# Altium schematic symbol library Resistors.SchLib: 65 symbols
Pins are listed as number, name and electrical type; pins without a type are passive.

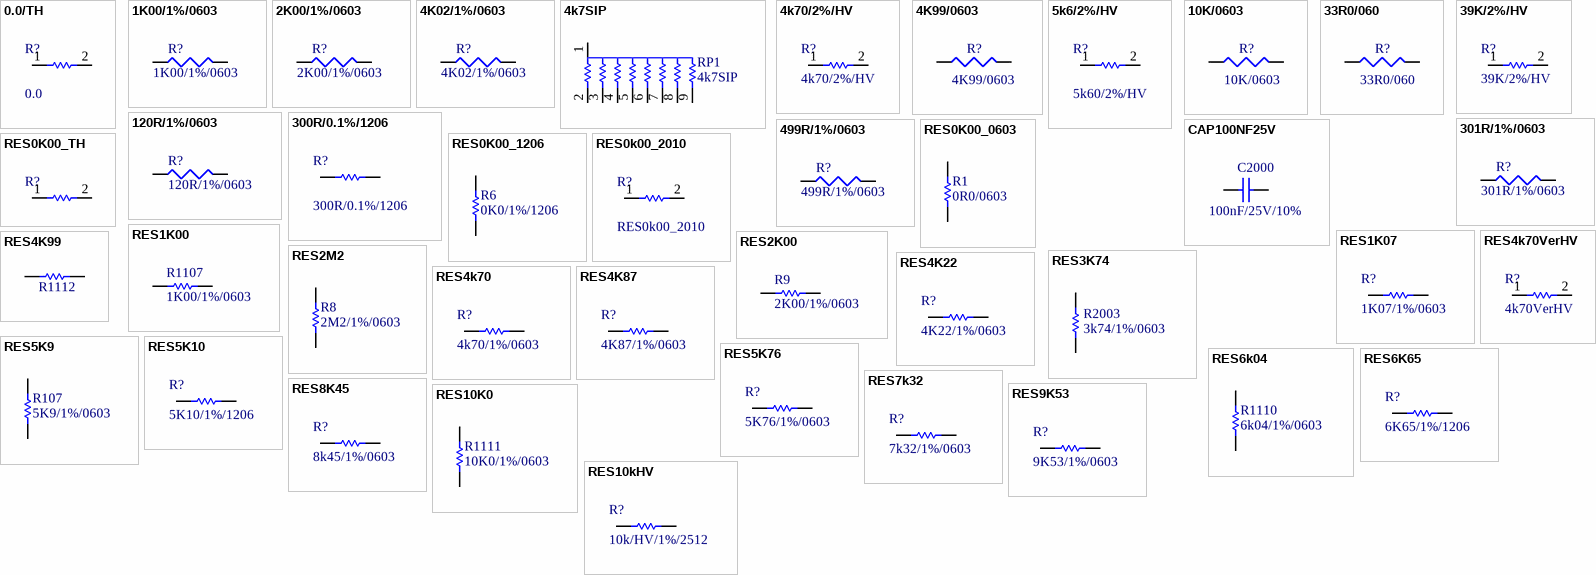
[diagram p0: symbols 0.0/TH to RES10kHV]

## 0.0/TH
designator R?, comment 0.0
0 Ohms Jumper 0.167W, 1/6W Through Hole Resistor Axial Carbon Film; MFG PN: ZOR-12-R-52-0R; DK PN: 0.0ETR-ND; MFG: Yageo; Comment_1: 0.0/TH
footprint Model Name (Footprint not found)
footprint ZEROOHM
pins: 1, 2
1 alternate drawing of the same symbol

## 1K00/1%/0603
designator R?
1 kOhms ±1% 0.1W, 1/10W Chip Resistor 0603 (1608 Metric) Moisture Resistant Thick Film; MFG: Yeago; MFG PN: RC0603FR-071KL; DK PN: 311-1.00KHRCT-ND
footprint 0603
pins: 1, 2

## 2K00/1%/0603
designator R?
2 kOhms ±1% 0.1W, 1/10W Chip Resistor 0603 (1608 Metric) Moisture Resistant Thick Film; MFG: Yeago; MFG PN: RC0603FR-072KL; DK PN: 311-2.00KHRCT-ND
footprint 0603
pins: 1, 2

## 4K02/1%/0603
designator R?
4.02 kOhms ±1% 0.1W, 1/10W Chip Resistor 0603 (1608 Metric) Moisture Resistant Thick Film; MFG: Yeago; MFG PN: RC0603FR-074K02L; DK PN: 311-4.02KHRCT-ND
footprint 0603
pins: 1, 2

## 4k7SIP
designator RP1
4.7k Ohm ±2% 200mW Power Per Element Bussed Resistor Network/Array ±100ppm/°C 9-SIP; MFG: Bournes; MFG PN: 4609X-101-472LF; DK PN: 4609X-101-472LF-ND
footprint SIP9
pins: 1, 2, 3, 4, 5, 6, 7, 8, 9

## 4k70/2%/HV
designator R?  Comment_1: 4k70/2%/HV  (hidden comment: *)
4.7 kOhms ±2% 1W Chip Resistor MELF, 0207 Anti-Sulfur, Automotive AEC-Q200, Pulse Withstanding Carbon Film; MFG PN: CMB02070X4701GB200; DK PN: CMB-4.7KCT-ND; MFG: Vishay
footprint CMB0207
pins: 1, 2
1 alternate drawing of the same symbol

## 4K99/0603
designator R?
RES 4.99K OHM 1/10W 1% 0603 SMD; MFG: Dale/Vishay; MFG PN: CRCW06034K99FKEAC; DK PN: 541-3985-1-ND
footprint 0603
pins: 1, 2

## 5k6/2%/HV
designator R?, comment 5k60/2%/HV
5.6 kOhms ±2% 1W Chip Resistor MELF, 0207 Anti-Sulfur, Automotive AEC-Q200, Pulse Withstanding Carbon Film; MFG PN: CMB02070X5601GB200; DK PN: CMB-5.6KCT-ND; MFG: Vishay
footprint CMB0207
pins: 1, 2
1 alternate drawing of the same symbol

## 10K/0603
designator R?
RES 10.0K OHM 1/10W 1% 0603 SMD; MFG: Dale/Vishay; MFG PN: CRCW060310K0FKEA; DK PN: 541-10.0KHCT-ND
footprint 0603
pins: 1, 2

## 33R0/060
designator R?
33 Ohms ±1% 0.1W, 1/10W Chip Resistor 0603 (1608 Metric) Moisture Resistant Thick Film; MFG: Yaego; MFG PN: RC0603FR-0733RL; DK PN: 311-33.0HRCT-ND
footprint 0603
pins: 1, 2

## 39K/2%/HV
designator R?
39 kOhms ±2% 1W Chip Resistor MELF, 0207 Anti-Sulfur, Automotive AEC-Q200, Pulse Withstanding Carbon Film; MFG PN: CMB02070X3902GB200; DK PN: CMB-39KCT-ND; MFG: Vishay
footprint CMB0207
pins: 1, 2
1 alternate drawing of the same symbol

## 120R/1%/0603
designator R?
120 Ohms ±1% 0.1W, 1/10W Chip Resistor 0603 (1608 Metric) Moisture Resistant Thick Film; MFG: Yaego; MFG PN: RC0603FR-07120RL; DK PN: 311-120HRCT-ND
footprint 0603
pins: 1, 2

## 300R/0.1%/1206
designator R?
300 Ohms ±0.1% 0.25W, 1/4W Chip Resistor 1206 (3216 Metric) Automotive AEC-Q200 Thin Film; MFG PN: ERA-8AEB301V; DK PN: P300BCCT-ND; MFG: Panasonic
footprint MY1206
pins: 1, 2
1 alternate drawing of the same symbol

## 301R/1%/0603
designator R?
301 Ohms ±1% 0.1W, 1/10W Chip Resistor 0603 (1608 Metric) Moisture Resistant Thick Film; MFG: Yeago; MFG PN: RC0603FR-07301RL; DK PN: 311-301HRCT-ND
footprint 0603
pins: 1, 2

## 499R/1%/0603
designator R?
499 Ohms ±1% 0.1W, 1/10W Chip Resistor 0603 (1608 Metric) Moisture Resistant Thick Film; MFG: Yeago; MFG PN: RC0603FR-07499RL; DK PN: 311-499HRCT-ND
footprint 0603
pins: 1, 2

## CAP100NF25V
designator C2000, comment 100nF/25V/10%
0.1µF ±10% 25V Ceramic Capacitor X7R 0603 (1608 Metric); MFG PN: 06033C104KAT2A; DK PN: 478-3714-1-ND; MFG: AVX
footprint MY0603
pins: 1, 2

## RES0K00_0603
designator R1, comment 0R0/0603
0.0 Ohm Jumper 0.1W, 1/10W Chip Resistor 0603 (1608 Metric) Moisture Resistant Thick Film; MFG PN: RC0603FR-070RL; DK PN: 311-0.0HRTR-ND; MFG: Yageo
footprint MY0603
pins: 1, 2
1 alternate drawing of the same symbol

## RES0K00_1206
designator R6  Comment_1: 0K0/1%/1206  (hidden comment: RES0K00_1206)
0.0 Ohm Jumper 0.25W, 1/4W Chip Resistor 1206 (3216 Metric) Moisture Resistant Thick Film; MFG PN: RC1206JR-070RL; DK PN: 311-0.0ERCT-ND; MFG: Yageo
footprint MY1206
pins: 1, 2
1 alternate drawing of the same symbol

## RES0k00_2010
designator R?
0 Ohms Jumper 0.75W, 3/4W Chip Resistor 2010 (5025 Metric) Automotive AEC-Q200 Thick Film; MFG PN: RMCF2010ZT0R00; DK PN: RMCF2010ZT0R00TR-ND; MFG: Stackpole
footprint CMB0207
pins: 1, 2
1 alternate drawing of the same symbol

## RES0K00_TH
designator R?, comment 0.0  (value not drawn)
0 Ohms Jumper 0.167W, 1/6W Through Hole Resistor Axial Carbon Film; MFG PN: ZOR-12-R-52-0R; DK PN: 0.0ETR-ND; MFG: Yageo
footprint JUMPER0.5
pins: 1, 2
1 alternate drawing of the same symbol

## RES1K00
designator R1107, comment 1K00/1%/0603
1.00k Ohm ±1% 0.1W, 1/10W Chip Resistor 0603 (1608 Metric) Moisture Resistant Thick Film; MFG PN: RC0603FR-071KL; DK PN: 311-1.00KHRTR-ND; MFG: Yageo
footprint MY0603
pins: 1, 2
1 alternate drawing of the same symbol

## RES1K07
designator R?, comment 1K07/1%/0603
1.00k Ohm ±1% 0.1W, 1/10W Chip Resistor 0603 (1608 Metric) Moisture Resistant Thick Film; MFG PN: RC0603FR-071K07L; DK PN: 311-1.07KHRTR-ND; MFG: Yageo
footprint MY0603
pins: 1, 2
1 alternate drawing of the same symbol

## RES2K00
designator R9, comment 2K00/1%/0603
2.00k Ohm ±1% 0.1W, 1/10W Chip Resistor 0603 (1608 Metric) Moisture Resistant Thick Film; MFG PN: RC0603FR-072KL; DK PN: 311-2.00KHRTR-ND; MFG: Yageo
footprint MY0603
pins: 1, 2
1 alternate drawing of the same symbol

## RES2M2
designator R8, comment 2M2/1%/0603
2.2M Ohm ±1% 0.1W, 1/10W Chip Resistor 0603 (1608 Metric) Moisture Resistant Thick Film; MFG PN: RC0603FR-072M2L; DK PN: YAG3329CT-ND; MFG: Yageo
footprint MY0603
pins: 1, 2
1 alternate drawing of the same symbol

## RES3K74
designator R2003, comment 3k74/1%/0603
3.74k Ohm ±1% 0.1W, 1/10W Chip Resistor 0603 (1608 Metric) Moisture Resistant Thick Film; MFG PN: RC0603FR-073K74L; DK PN: 311-3.74KHRTR-ND; MFG: Yageo
footprint MY0603
pins: 1, 2
1 alternate drawing of the same symbol

## RES4K22
designator R?, comment 4K22/1%/0603
4.22k Ohm ±1% 0.1W, 1/10W Chip Resistor 0603 (1608 Metric) Moisture Resistant Thick Film; MFG PN: RC0603FR-074K22L; DK PN: 311-4.22KHRTR-ND; MFG: Yageo
footprint MY0603
pins: 1, 2
1 alternate drawing of the same symbol

## RES4k70
designator R?, comment 4k70/1%/0603
4.7k Ohm ±1% 0.1W, 1/10W Chip Resistor 0603 (1608 Metric) Moisture Resistant Thick Film; MFG PN: RC0603FR-074K7L; DK PN: 311-4.70KHRTR-ND; MFG: Yageo
footprint MY0603
pins: 1, 2
1 alternate drawing of the same symbol

## RES4k70VerHV
designator R?, comment 4k70VerHV
4.7 kOhms ±5% 1W Through Hole Resistor Axial Flame Retardant Coating, Pulse Withstanding, Safety Metal Film; MFG PN: ASRM1JA4K70; DK PN: ASRM1JA4K70CT-ND; MFG: Stackpole
footprint ASR1_VERT
pins: 1, 2
1 alternate drawing of the same symbol

## RES4K87
designator R?, comment 4K87/1%/0603
4.87k Ohm ±1% 0.1W, 1/10W Chip Resistor 0603 (1608 Metric) Moisture Resistant Thick Film; MFG PN: RC0603FR-074K87L; DK PN: 311-4.87KHRTR-ND; MFG: Yageo
footprint MY0603
pins: 1, 2
1 alternate drawing of the same symbol

## RES4K99
designator R1112  (value not drawn)
4.99k Ohm ±1% 0.1W, 1/10W Chip Resistor 0603 (1608 Metric) Moisture Resistant Thick Film; MFG PN: RC0603FR-074K99L; DK PN: 311-4.99KHRTR-ND; MFG: Yageo; Comment_1: 4K99/1%/0603
footprint MY0603
pins: 1, 2
1 alternate drawing of the same symbol

## RES5K9
designator R107, comment 5K9/1%/0603
5.9k Ohm ±1% 0.1W, 1/10W Chip Resistor 0603 (1608 Metric) Moisture Resistant Thick Film; MFG PN: RC0603FR-075K9L; DK PN: 311-5.90KHRTR-ND; MFG: Yageo
footprint MY0603
pins: 1, 2
1 alternate drawing of the same symbol

## RES5K10
designator R?, comment 5K10/1%/1206
5.1k Ohm ±1% 0.25W, 1/4W Chip Resistor 1206 (3216 Metric) Automotive AEC-Q200, High Voltage Thick Film; MFG PN: KTR18EZPF5101; DK PN: RHM5.10KAICT-ND; MFG: Rohm
footprint MY1206
pins: 1, 2
1 alternate drawing of the same symbol

## RES5K76
designator R?, comment 5K76/1%/0603
5.76k Ohm ±1% 0.1W, 1/10W Chip Resistor 0603 (1608 Metric) Moisture Resistant Thick Film; MFG PN: RC0603FR-075K76L; DK PN: 311-5.76KHRCT-ND; MFG: Yageo
footprint MY0603
pins: 1, 2
1 alternate drawing of the same symbol

## RES6k04
designator R1110, comment 6k04/1%/0603
6.04 kOhms ±1% 0.1W, 1/10W Chip Resistor 0603 (1608 Metric) Automotive AEC-Q200 Thick Film; MFG PN: ERJ-3EKF6041V; DK PN: P6.04KHDKR-ND; MFG: Panasonic
footprint MY0603
pins: 1, 2
1 alternate drawing of the same symbol

## RES6K65
designator R?, comment 6K65/1%/1206
6.65 kOhms ±1% 0.25W, 1/4W Chip Resistor 1206 (3216 Metric) Automotive AEC-Q200, High Voltage Thick Film; MFG PN: KTR18EZPF6651; DK PN: RHM6.65KAICT-ND; MFG: Rohm
footprint MY1206
pins: 1, 2
1 alternate drawing of the same symbol

## RES7k32
designator R?, comment 7k32/1%/0603
7.32 kOhms ±1% 0.1W, 1/10W Chip Resistor 0603 (1608 Metric) Moisture Resistant Thick Film; MFG PN: RC0603FR-077K32L; DK PN: 311-7.32KHRCT-ND; MFG: Yageo
footprint MY0603
pins: 1, 2
1 alternate drawing of the same symbol

## RES8K45
designator R?, comment 8k45/1%/0603
8.45k Ohm ±1% 0.1W, 1/10W Chip Resistor 0603 (1608 Metric) Moisture Resistant Thick Film; MFG PN: RC0603FR-078K45L; DK PN: 311-8.45KHRTR-ND; MFG: Yageo
footprint MY0603
pins: 1, 2
1 alternate drawing of the same symbol

## RES9K53
designator R?, comment 9K53/1%/0603
9.53k Ohm ±1% 0.1W, 1/10W Chip Resistor 0603 (1608 Metric) Moisture Resistant Thick Film; MFG PN: RC0603FR-079K53L; DK PN: 311-9.53KHRTR-ND; MFG: Yageo
footprint MY0603
pins: 1, 2
1 alternate drawing of the same symbol

## RES10K0
designator R1111, comment 10K0/1%/0603
10k Ohm ±1% 0.1W, 1/10W Chip Resistor 0603 (1608 Metric) Moisture Resistant Thick Film; MFG PN: RC0603FR-0710KL; DK PN: 311-10.0KHRTR-ND; MFG: Yageo
footprint MY0603
pins: 1, 2
1 alternate drawing of the same symbol

## RES10kHV
designator R?, comment 10k/HV/1%/2512
10k Ohm ±1% 2W Chip Resistor 2512 (6432 Metric) High Voltage, Pulse Withstanding Thick Film; MFG PN: HVCB2512FDD10K0; DK PN: HVCB2512FDD10K0TR-ND; MFG: Stackpole
footprint HVC2512
pins: 1, 2
1 alternate drawing of the same symbol

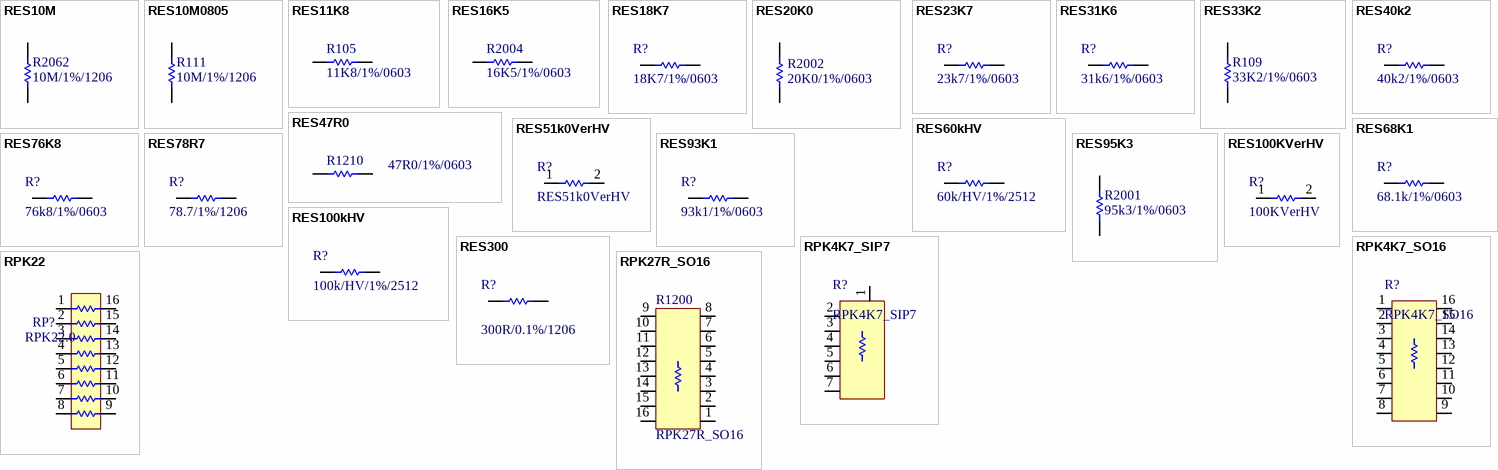
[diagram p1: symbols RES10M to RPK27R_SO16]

## RES10M
designator R2062, comment 10M/1%/1206
10 MOhms ±1% 0.25W, 1/4W Chip Resistor 1206 (3216 Metric) Automotive AEC-Q200, High Voltage Thick Film; MFG PN: KTR18EZPF1005; DK PN: RHM10.0MAICT-ND; MFG: Rohm
footprint MY1206
pins: 1, 2
1 alternate drawing of the same symbol

## RES10M0805
designator R111, comment 10M/1%/1206
10 MOhms ±1% 0.125W, 1/8W Chip Resistor 0805 (2012 Metric) Moisture Resistant Thick Film; MFG PN: RC2012F106CS; DK PN: 1276-5465-2-ND; MFG: Samsung
footprint MY0805
pins: 1, 2
1 alternate drawing of the same symbol

## RES11K8
designator R105, comment 11K8/1%/0603
11.8k Ohm ±1% 0.1W, 1/10W Chip Resistor 0603 (1608 Metric) Moisture Resistant Thick Film; MFG PN: 311-11.8KHRTR-ND; DK PN: RC0603FR-0711K8L; MFG: Yageo
footprint MY0603
pins: 1, 2
1 alternate drawing of the same symbol

## RES16K5
designator R2004, comment 16K5/1%/0603
16.5k Ohm ±1% 0.1W, 1/10W Chip Resistor 0603 (1608 Metric) Moisture Resistant Thick Film; MFG PN: RC0603FR-0716K5L; DK PN: 311-16.5KHRTR-ND; MFG: Yageo
footprint MY0603
pins: 1, 2
1 alternate drawing of the same symbol

## RES18K7
designator R?, comment 18K7/1%/0603
18.7k Ohm ±1% 0.1W, 1/10W Chip Resistor 0603 (1608 Metric) Moisture Resistant Thick Film; MFG PN: RC0603FR-0718K7L; DK PN: 311-18.7KHRTR-ND; MFG: Yageo
footprint MY0603
pins: 1, 2
1 alternate drawing of the same symbol

## RES20K0
designator R2002, comment 20K0/1%/0603
20k Ohm ±1% 0.1W, 1/10W Chip Resistor 0603 (1608 Metric) Moisture Resistant Thick Film; MFG PN: RC0603FR-0720KL; DK PN: 311-20.0KHRTR-ND; MFG: Yageo
footprint MY0603
pins: 1, 2
1 alternate drawing of the same symbol

## RES23K7
designator R?, comment 23k7/1%/0603
23.7k Ohm ±1% 0.1W, 1/10W Chip Resistor 0603 (1608 Metric) Moisture Resistant Thick Film; MFG PN: RC0603FR-0723K7L; DK PN: 311-23.7KHRTR-ND; MFG: Yageo
footprint MY0603
pins: 1, 2
1 alternate drawing of the same symbol

## RES31K6
designator R?, comment 31k6/1%/0603
31.6k Ohm ±1% 0.1W, 1/10W Chip Resistor 0603 (1608 Metric) Moisture Resistant Thick Film; MFG PN: RC0603FR-0731K6L; DK PN: 311-31.6KHRTR-ND; MFG: Yageo
footprint MY0603
pins: 1, 2
1 alternate drawing of the same symbol

## RES33K2
designator R109, comment 33K2/1%/0603
33.2 kOhms ±1% 0.1W, 1/10W Chip Resistor 0603 (1608 Metric) Moisture Resistant Thick Film; MFG PN: RC0603FR-0733K2L; DK PN: 311-33.2KHRTR-ND; MFG: Yageo
footprint MY0603
pins: 1, 2
1 alternate drawing of the same symbol

## RES40k2
designator R?, comment 40k2/1%/0603
40.2k Ohm ±1% 0.1W, 1/10W Chip Resistor 0603 (1608 Metric) Moisture Resistant Thick Film; MFG PN: RC0603FR-0740K2L; DK PN: 311-40.2KHRTR-ND; MFG: Yageo
footprint MY0603
pins: 1, 2
1 alternate drawing of the same symbol

## RES47R0
designator R1210, comment 47R0/1%/0603
47 Ohm ±1% 0.1W, 1/10W Chip Resistor 0603 (1608 Metric) Moisture Resistant Thick Film; MFG PN: RC0603FR-0747RL; DK PN: 311-47.0HRTR-ND; MFG: Yageo
footprint MY0603
pins: 1, 2
1 alternate drawing of the same symbol

## RES51k0VerHV
designator R?
51 kOhms ±5% 1W Through Hole Resistor Axial Flame Retardant Coating, Pulse Withstanding, Safety Metal Film; MFG PN: ASRM1JA51K0; DK PN: ASRM1JA51K0-ND; MFG: Stackpole
footprint ASR1_VERT
pins: 1, 2
1 alternate drawing of the same symbol

## RES60kHV
designator R?, comment 60k/HV/1%/2512
60k Ohm ±1% 2W Chip Resistor 2512 (6432 Metric) High Voltage, Pulse Withstanding Thick Film; MFG PN: HVCB2512FDD60K0; DK PN: HVCB2512FDD60K0CT-ND; MFG: Stackpole
footprint HVC2512
pins: 1, 2
1 alternate drawing of the same symbol

## RES68K1
designator R?, comment 68.1k/1%/0603
68.1k Ohm ±1% 0.1W, 1/10W Chip Resistor 0603 (1608 Metric) Moisture Resistant Thick Film; MFG PN: RC0603FR-0768K1L; DK PN: 311-68.1KHRTR-ND; MFG: Yageo
footprint MY0603
pins: 1, 2
1 alternate drawing of the same symbol

## RES76K8
designator R?, comment 76k8/1%/0603
76.8k Ohm ±1% 0.1W, 1/10W Chip Resistor 0603 (1608 Metric) Moisture Resistant Thick Film; MFG PN: RC0603FR-0776K8L; DK PN: 311-76.8KHRCT-ND; MFG: Yageo
footprint MY0603
pins: 1, 2
1 alternate drawing of the same symbol

## RES78R7
designator R?, comment 78.7/1%/1206
78.7 Ohms ±1% 0.25W, 1/4W Chip Resistor 1206 (3216 Metric) Moisture Resistant Thick Film; MFG PN: RC1206FR-0778R7L; DK PN: 311-78.7FRCT-ND; MFG: Yageo
footprint MY1206
pins: 1, 2
1 alternate drawing of the same symbol

## RES93K1
designator R?, comment 93k1/1%/0603
93.1k Ohm ±1% 0.1W, 1/10W Chip Resistor 0603 (1608 Metric) Moisture Resistant Thick Film; MFG PN: RC0603FR-0793K1L; DK PN: 311-93.1KHRCT-ND; MFG: Yageo
footprint MY0603
pins: 1, 2
1 alternate drawing of the same symbol

## RES95K3
designator R2001, comment 95k3/1%/0603
95.3k Ohm ±1% 0.1W, 1/10W Chip Resistor 0603 (1608 Metric) Moisture Resistant Thick Film; MFG PN: RC0603FR-0795K3L; DK PN: 311-95.3KHRTR-ND; MFG: Yageo
footprint MY0603
pins: 1, 2
1 alternate drawing of the same symbol

## RES100kHV
designator R?, comment 100k/HV/1%/2512
100k Ohm ±1% 2W Chip Resistor 2512 (6432 Metric) High Voltage, Pulse Withstanding Thick Film; MFG PN: HVCB2512FKC100K; DK PN: HVCB2512FKC100KCT-ND; MFG: Stackpole
footprint HVC2512
pins: 1, 2
1 alternate drawing of the same symbol

## RES100KVerHV
designator R?, comment 100KVerHV
100 kOhms ±5% 1W Through Hole Resistor Axial Flame Retardant Coating, Pulse Withstanding, Safety Metal Film; MFG PN: ASRM1JA100K; DK PN: ASRM1JA100KCT-ND; MFG: Stackpole
footprint ASR1_VERT
pins: 1, 2
1 alternate drawing of the same symbol

## RES300
designator R?, comment 300R/0.1%/1206
300 Ohms ±0.1% 0.25W, 1/4W Chip Resistor 1206 (3216 Metric) Automotive AEC-Q200 Thin Film; MFG PN: ERA-8AEB301V; DK PN: P300BCCT-ND; MFG: Panasonic; Comment_1: 3R00/0.1%/1206
footprint MY1206
pins: 1, 2
1 alternate drawing of the same symbol

## RPK4K7_SIP7
designator R?
4.7k Ohm ±2% 200mW Power Per Element Bussed Resistor Network/Array ±100ppm/°C 7-SIP; MFG PN: 4607X-101-472LF; DK PN: 4607X-101-472LF-ND; MFG: Bourns
footprint Model Name (Footprint not found)
footprint RES_SIP7
pins: 1, 2, 3, 4, 5, 6, 7
1 alternate drawing of the same symbol

## RPK4K7_SO16
designator R?
4.7k Ohm ±2% 160mW Power Per Element Isolated Resistor Network/Array ±100ppm/°C 16-SOIC (0.220", 5.59mm Width); MFG PN: 4816P-T01-472LF; DK PN: 4816P-T01-472LF-ND; MFG: Bourns
footprint Model Name (Footprint not found)
footprint SO_RPK16
pins: 1, 2, 3, 4, 5, 6, 7, 8, 9, 10, 11, 12, 13, 14, 15, 16
1 alternate drawing of the same symbol

## RPK22
designator RP?, comment RPK22.0
22 Ohm ±1Ohm 160mW Power Per Element Isolated Resistor Network/Array ±250ppm/°C 16-SOIC (0.220", 5.59mm Width); MFG: Bourns; MFG PN: 4816P-1-220LF; DK PN: 4816P-1-220LFCT-ND
footprint RPK4816
pins: 1, 2 1, 3 1, 4 1, 5 1, 6 1, 7 1, 8 1, 9 2, 10 2, 11 2, 12 2, 13 2, 14 2, 15 2, 16 2

## RPK27R_SO16
designator R1200
27 Ohm ±1 Ohm 160mW Power Per Element Isolated Resistor Network/Array ±250ppm/°C 16-SOIC (0.220", 5.59mm Width); MFG PN: 4816P-T01-270LF; DK PN: 4816P-T01-270LF-ND; MFG: Bourns
footprint Model Name (Footprint not found)
footprint SO_RPK16
pins: 1, 2, 3, 4, 5, 6, 7, 8, 9, 10, 11, 12, 13, 14, 15, 16
1 alternate drawing of the same symbol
